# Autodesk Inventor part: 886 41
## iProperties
Created: 2005-11
Part Number: 886 41
Material: 1.4301 X5CrNi10-10 A2
Description: Flansch DN100 ISO-K
Document SubType Name: Modellieren
Designer: Mittelmeyer
Manufacturer: Standard
Standards Organization: Custom
Author: Mittelmeyer
Comments: LEYBOLD
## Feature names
1. Extrusion2
2. Extrusion3
3. Extrusion4
4. Drehung1 [Revolution]
5. Bohrung1 [Hole]
